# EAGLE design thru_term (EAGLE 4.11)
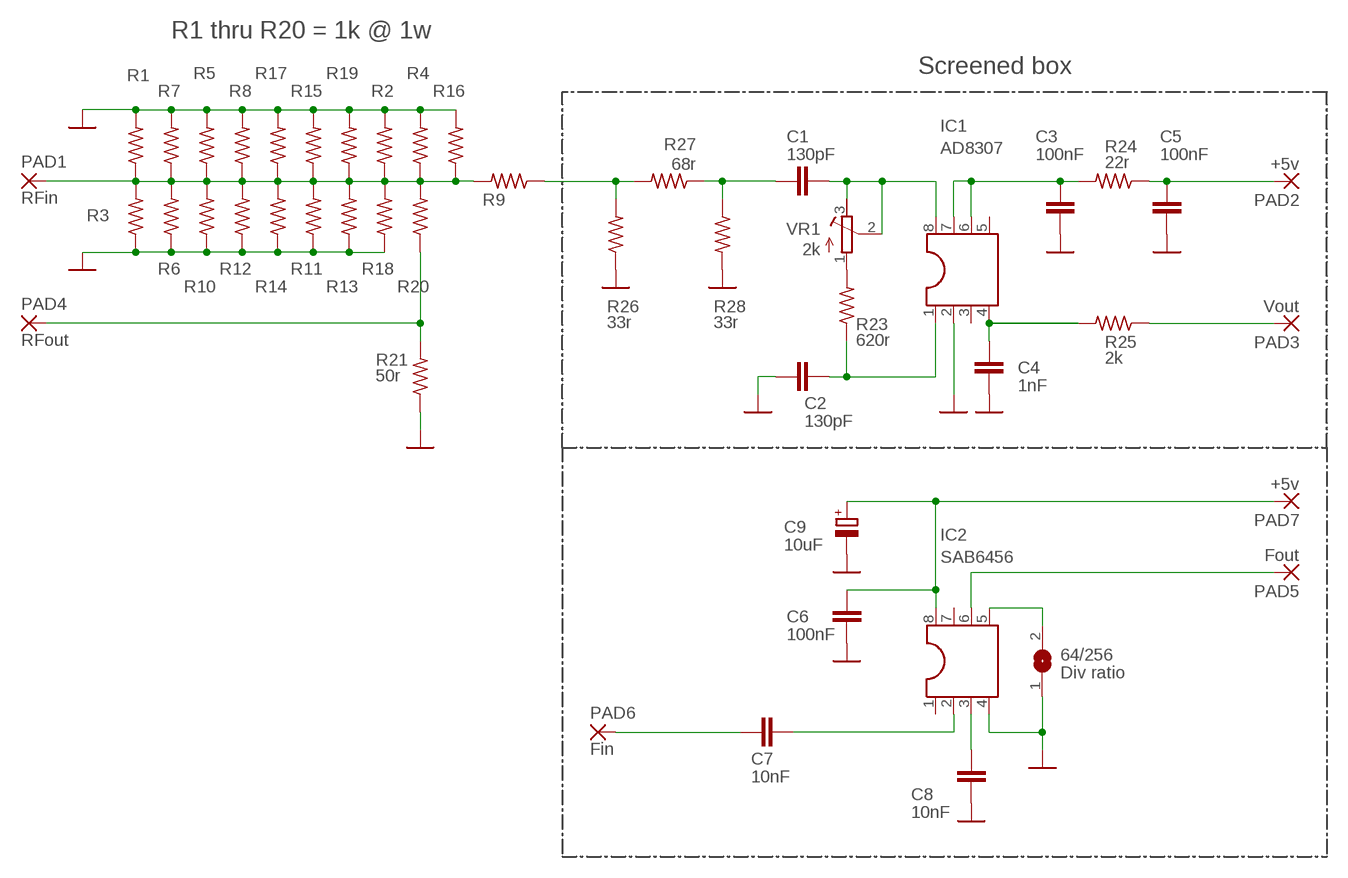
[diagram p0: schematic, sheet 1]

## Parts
64/256  SJ  [SJ]
C1  130pF  C-EUC0805K  [C0805K]
C2  130pF  C-EUC0805K  [C0805K]
C3  100nF  C-EUC0805K  [C0805K]
C4  1nF  C-EUC0805K  [C0805K]
C5  100nF  C-EUC0805K  [C0805K]
C6  100nF  C-EUC0805K  [C0805K]
C7  10nF  C-EUC0805K  [C0805K]
C8  10nF  C-EUC0805K  [C0805K]
C9  10uF  CPOL-EUA/3216-18R  [A/3216-18R]
IC1  AD8307  DIL8  [DIL08]
IC2  SAB6456  DIL8  [DIL08]
PAD1  RFin  2,54/0,8  [2,54/0,8]
PAD2  +5v  2,54/0,8  [2,54/0,8]
PAD3  Vout  2,54/0,8  [2,54/0,8]
PAD4  RFout  2,54/0,8  [2,54/0,8]
PAD5  Fout  2,54/0,8  [2,54/0,8]
PAD6  Fin  2,54/0,8  [2,54/0,8]
PAD7  +5v  2,54/0,8  [2,54/0,8]
R1  R-US_R1206  [R1206]
R2  R-US_R1206  [R1206]
R3  R-US_R1206  [R1206]
R4  R-US_R1206  [R1206]
R5  R-US_R1206  [R1206]
R6  R-US_R1206  [R1206]
R7  R-US_R1206  [R1206]
R8  R-US_R1206  [R1206]
R9  R-US_R1206  [R1206]
R10  R-US_R1206  [R1206]
R11  R-US_R1206  [R1206]
R12  R-US_R1206  [R1206]
R13  R-US_R1206  [R1206]
R14  R-US_R1206  [R1206]
R15  R-US_R1206  [R1206]
R16  R-US_R1206  [R1206]
R17  R-US_R1206  [R1206]
R18  R-US_R1206  [R1206]
R19  R-US_R1206  [R1206]
R20  R-US_R1206  [R1206]
R21  50r  R-US_M0805  [M0805]
R23  620r  R-US_M0805  [M0805]
R24  22r  R-US_M0805  [M0805]
R25  2k  R-US_M0805  [M0805]
R26  33r  R-US_M1206  [M1206]
R27  68r  R-US_M1206  [M1206]
R28  33r  R-US_M1206  [M1206]
VR1  2k  R-TRIMM4G/J  [RTRIM4G/J]

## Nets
GND: 64/256.1 C2.1 C3.1 C4.1 C5.1 C6.1 C8.1 C9.- IC1.2 IC2.4 R1.2 R2.2 R3.1 R4.2 R5.2 R6.1 R7.2 R8.2 R10.1 R11.1 R12.1 R13.1 R14.1 R15.2 R16.2 R17.2 R18.1 R19.2 R21.1 R26.1 R28.2
N$1: R23.2 VR1.1(E)
N$2: C1.2 IC1.8 VR1.2(S) VR1.3(A)
N$3: C2.2 IC1.1 R23.1
N$4: C3.2 IC1.6 IC1.7 R24.2
N$5: C4.2 IC1.4 R25.2
N$6: PAD1.1(P) R1.1 R2.1 R3.2 R4.1 R5.1 R6.2 R7.1 R8.1 R9.2 R10.2 R11.2 R12.2 R13.2 R14.2 R15.1 R16.1 R17.1 R18.2 R19.1 R20.2
N$7: C5.2 PAD2.1(P) R24.1
N$8: PAD3.1(P) R25.1
N$9: C1.1 R27.1 R28.1
N$10: C7.1 IC2.2
N$12: C8.2 IC2.3
N$13: C6.2 C9.+ IC2.8 PAD7.1(P)
N$14: 64/256.2 IC2.5
N$15: IC2.6 PAD5.1(P)
N$16: C7.2 PAD6.1(P)
N$17: R9.1 R26.2 R27.2
N$18: PAD4.1(P) R20.1 R21.2
Unconnected: IC1.3 IC1.5 IC2.1 IC2.7

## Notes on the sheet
- R1 thru R20 = 1k @ 1w
- Screened box
- Div ratio

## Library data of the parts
64/256 = jumper:SJ: SMD solder JUMPER
C1-C8 = rcl:C-EU: CAPACITOR, European symbol
C9 = rcl:CPOL-EU: POLARIZED CAPACITOR, European symbol
IC1 IC2 = ic-package:DIL8: Dual In Line
PAD1-PAD7 = wirepad:2,54/0,8: THROUGH-HOLE PAD
R1-R21 R23-R28 = rcl:R-US_: RESISTOR, American symbol
VR1 = rcl:R-TRIMM: Trimm resistor

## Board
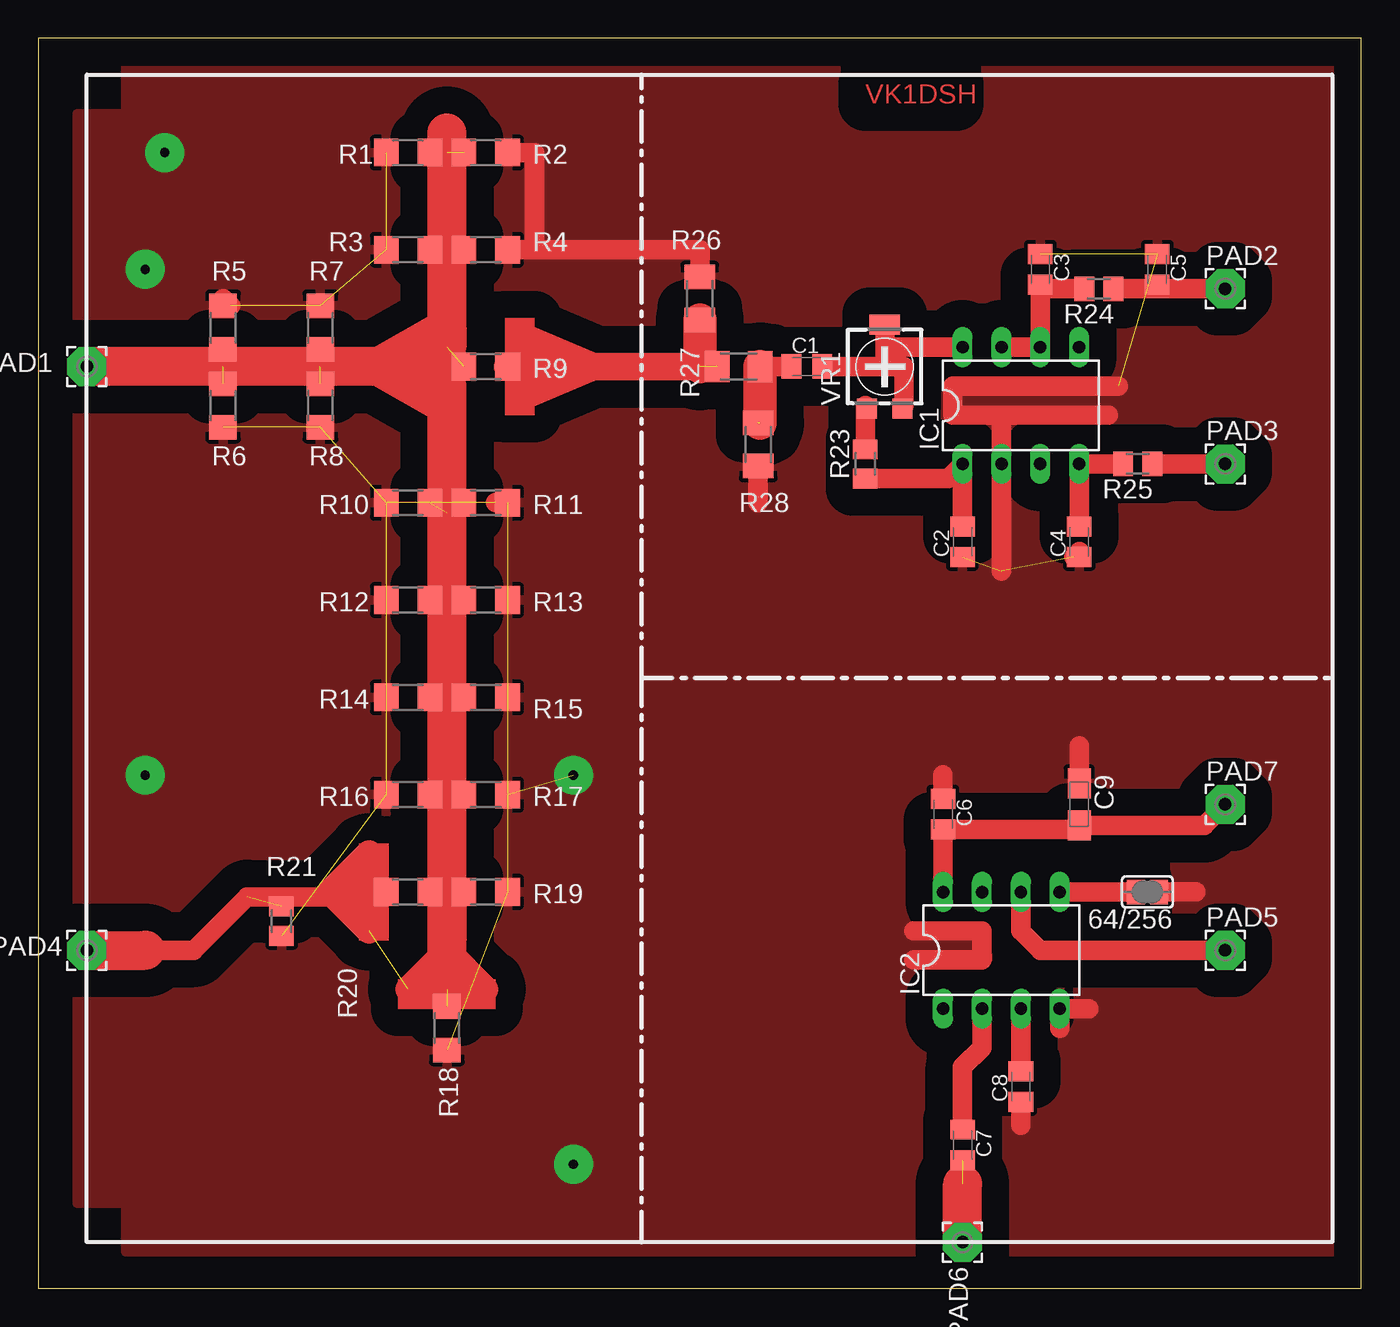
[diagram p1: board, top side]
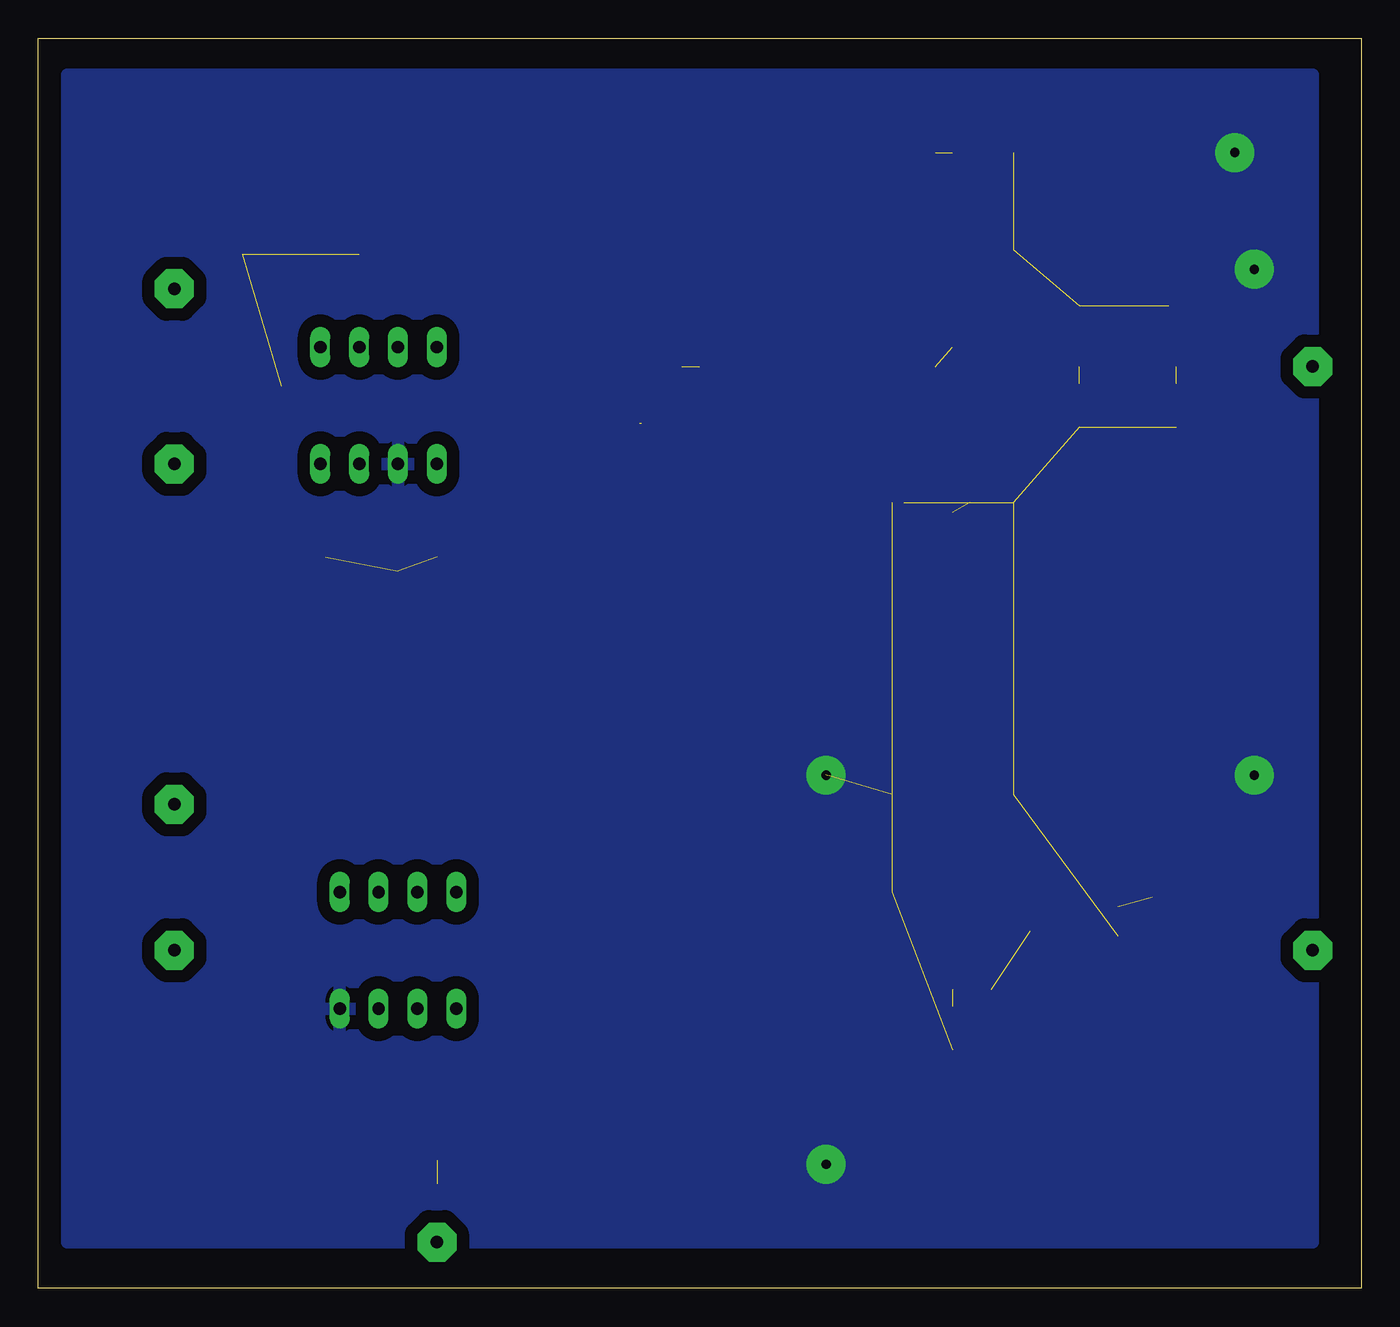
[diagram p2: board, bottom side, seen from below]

Size 86.34 x 81.58 mm. Coordinates in mm from the lower left corner, seen from the top.
Outline: 0,0 86.34,0 86.34,81.58 0,81.58 0,0
Copper layers (1*16): Top 0.035mm / dielectric 1.5mm / Bottom 0.035mm
Design rules "default": minimum track width 10mil, minimum drill 24mil, track to track 8mil, track to pad 8mil, pad to pad 8mil, via to via 8mil, smd to smd 8mil, copper to edge 40mil, drill to drill 8mil, minimum pad ring 10mil, minimum via ring 8mil, stop-mask expansion 4mil, vias tented up to drill 0mil, thermal gap 10mil

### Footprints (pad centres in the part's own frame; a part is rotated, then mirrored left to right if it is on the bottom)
SJ = smd 1.168 x 1.6: 1 -0.762,0; 2 0.762,0
C0805K = smd 1.3 x 1.6: 1 -1,0; 2 1,0
A/3216-18R = smd 1.95 x 1.5: + 1.375,0; - -1.375,0
DIL08 = drill 0.813 long: 1 -3.81,-3.81; 2 -1.27,-3.81; 3 1.27,-3.81; 4 3.81,-3.81; 5 3.81,3.81; 6 1.27,3.81; 7 -1.27,3.81; 8 -3.81,3.81
2,54/0,8 = drill 0.813 pad 2.54 octagon: 1 0,0
R1206 = smd 1.6 x 1.803: 1 -1.422,0; 2 1.422,0
M0805 = smd 1.3 x 1.6: 1 -0.95,0; 2 0.95,0
M1206 = smd 1.6 x 2: 1 -1.4,0; 2 1.4,0
RTRIM4G/J = smd 1.3 x 1.3: 1 -1.15,-2.75; 3 1.15,-2.75 | smd 2 x 1.3: 2 0,2.75

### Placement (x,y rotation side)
64/256  72.38,25.87 180 top
C1  50.16,60.16 0 top
C2  60.32,48.73 90 top
C3  65.4,66.51 270 top
C4  67.94,48.73 90 top
C5  73.02,66.51 270 top
C6  59.05,30.95 270 top
C7  60.32,9.36 270 top
C8  64.13,13.17 90 top
C9  67.94,31.58 270 top
IC1  64.13,57.62 0 top
IC2  62.86,22.06 0 top
PAD1  3.17,60.16 0 top
PAD2  77.46,65.24 0 top
PAD3  77.46,53.81 0 top
PAD4  3.17,22.06 0 top
PAD5  77.46,22.06 0 top
PAD6  60.32,3.01 0 top
PAD7  77.46,31.58 0 top
R1  24.12,74.13 180 top
R2  29.2,74.13 0 top
R3  24.12,67.78 0 top
R4  29.2,67.78 0 top
R5  12.06,62.7 90 top
R6  12.06,57.62 90 top
R7  18.41,62.7 90 top
R8  18.41,57.62 270 top
R9  29.2,60.16 180 top
R10  24.12,51.27 0 top
R11  29.2,51.27 180 top
R12  24.12,44.92 0 top
R13  29.2,44.92 180 top
R14  24.12,38.57 0 top
R15  29.2,38.57 0 top
R16  24.12,32.22 180 top
R17  29.2,32.22 0 top
R18  26.66,16.98 90 top
R19  29.2,25.87 0 top
R20  24.12,25.87 0 top
R21  15.87,23.96 90 top
R23  53.97,53.81 90 top
R24  69.21,65.24 180 top
R25  71.75,53.81 180 top
R26  43.18,64.61 270 top
R27  45.72,60.16 180 top
R28  46.98,55.08 270 top
VR1  55.24,60.16 0 top

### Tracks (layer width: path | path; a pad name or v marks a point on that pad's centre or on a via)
GND  (via drill 0.61 pad 2.54)  (20 unrouted)
  Top 1.27: C4.1 67.94,48.09 67.57,47.73 | R6.1 12.06,56.35 | R11.1 29.84,51.27 | 31.11,74.13 R2.2 32.38,74.13 32.38,67.78 31.11,67.78 | R5.2 12.06,64.61 12.54,64.12 | 62.86,56.98 IC1.2 62.86,46.82 | 68.57,18.25 IC2.4 66.67,16.98 | 57.15,23.33 61.59,23.33 61.59,21.42 57.15,21.42 | 70.48,58.89 59.69,58.89 59.69,56.98 69.84,56.98 | 64/256.1 75.56,25.87 | C9.- 67.94,35.39 | C6.1 59.05,33.49 | C8.1 64.13,10.63 | R28.2 46.98,51.27 | R4.2 31.11,67.78 | R26.1 43.18,67.78 31.11,67.78
  other vias: 8.25,74.13 6.98,33.49 34.92,33.49 34.92,8.09 6.98,66.51
  pour Bottom (isolate 0.813): 3.17,3.01 3.17,79.21 84.45,79.21 84.45,3.01
  pour Top (isolate 1.778): 5.71,2.38 5.71,5.55 2.54,5.55 2.54,76.67 5.71,76.67 5.71,79.84 85.08,79.84 85.08,2.38
N$1
  Top 1.27: VR1.1 54.09,57.5 53.97,57.62 R23.2
N$2
  Top 1.27: IC1.8 55.24,61.43 55.24,62.7 | 55.24,62.7 VR1.2 | C1.2 55.24,60.16 | VR1.3 56.39,57.5 56.51,57.62 56.51,60.16 55.24,60.16 | 55.24,60.16 55.24,62.7
N$3
  Top 1.27: C2.2 IC1.1 59.37,52.86 R23.1
N$4
  Top 1.27: IC1.7 IC1.6 65.4,65.24 | 65.4,65.24 C3.2 | 65.4,65.24 R24.2
N$5
  Top 1.27: R25.2 IC1.4 C4.2
N$6  (6 unrouted)
  Top 1.27: 12.06,60.16 R5.1 | 18.41,60.16 R7.1 | 26.66,74.13 R1.1 | R3.2 26.66,67.78 R4.1 | R11.2 27.15,51.12 26.66,50.63 | R13.2 26.66,44.92 R12.2 | R15.1 26.66,38.57 R14.2 | R16.1 26.66,32.22 R17.1 | R20.2 26.66,25.87 R19.1 27.93,25.87
  Top 2.54: 22.22,60.16 25.39,60.16 | 22.22,60.16 18.41,60.16 12.06,60.16 PAD1.1 | 25.39,60.16 26.66,61.43 26.66,62.7 | 26.66,62.7 26.66,67.78 26.66,74.13 26.66,75.4 | 25.39,60.16 26.66,58.89 26.66,57.62 | 26.66,25.87 26.66,22.7 | 26.66,25.87 26.66,32.22 26.66,38.57 26.66,44.92 26.66,50.63 26.66,57.62 | 22.22,60.16 26.66,62.7 | 26.66,57.62 22.22,60.16 | 26.66,19.52 26.66,25.87
N$7
  Top 1.27: 73.02,65.24 75.56,65.24 | 75.56,65.24 76.19,65.24 | 73.02,65.24 C5.2 | R24.1 73.02,65.24 | 75.56,65.24 PAD2.1
N$8
  Top 1.27: R25.1 PAD3.1
N$9  (1 unrouted)
  Top 1.27: R27.1 C1.1
  Top 2.184: 47.12,56.48 R27.1
N$10
  Top 1.27: IC2.2 61.59,15.71 60.32,14.44 C7.1
N$12
  Top 1.27: C8.2 IC2.3
N$13
  Top 1.27: IC2.8 C6.2 67.94,29.95 C9.+ | C9.+ 67.94,30.31 | C9.+ 76.09,30.21 PAD7.1
N$14
  Top 1.27: IC2.5 64/256.2
N$15
  Top 1.27: PAD5.1 65.4,22.06 64.13,23.33 IC2.6
N$16  (1 unrouted)
  Top 2.54: PAD6.1 60.32,6.82
N$17  (1 unrouted)
  Top 1.778: R9.1 36.19,60.16 | 36.19,60.16 43.18,60.16 | 36.19,60.16 31.74,62.06 | 36.19,60.16 31.74,58.25
  Top 2.184: 43.18,60.16 R26.2
N$18  (2 unrouted)
  Top 1.27: R20.1 19.04,25.87 18.72,25.55 13.65,25.55 10.16,22.06 6.98,22.06
  Top 1.676: 21.58,28.41 21.58,23.33 19.04,25.87 21.58,28.41 | 24.12,19.52 29.2,19.52 26.66,22.06 24.12,19.52
  Top 2.54: PAD4.1 6.98,22.06
(copper drawn outside any net)
  shapes: Top area x3

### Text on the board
Top: VK1DSH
